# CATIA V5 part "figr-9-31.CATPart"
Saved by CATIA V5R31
Part number: Part1
Bounding box of the stored display mesh (mm): x -60 to 60, y -41.231 to 41.231, z -41.231 to 41.231
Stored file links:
  D:\PROJECTS\Project 2021\US EDITION\CATIA V5 6R 2021\Resources\Part Files\c09_catia_v5_6r2021_prt\c09_catia_v5_6r2021_prt\figr-9-31.CATPart
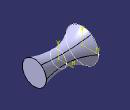
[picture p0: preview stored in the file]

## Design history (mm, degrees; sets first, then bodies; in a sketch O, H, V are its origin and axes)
Body1 (main body)
  Sketch1 on yz-plane, origin (0, 0, 0), H (0, 1, 0), V (0, 0, 1)
    circle A1 centre (0, 0) radius 20
  Plane1: type Offset, RefPlane yz-plane, Offset 60
  Plane2: type Offset, RefPlane yz-plane, Offset -60
  Sketch2 on Plane1, origin (60, 0, 0), H (0, 1, 0), V (0, 0, 1)
    circle A1 centre (0, 0) radius 30
  Sketch3 on Plane2, origin (-60, 0, 0), H (0, 1, 0), V (0, 0, 1)
    circle A1 centre (0, 0) radius 41.2311
  Loft1: solid, Sections (Sketch2; Sketch1; Sketch3)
